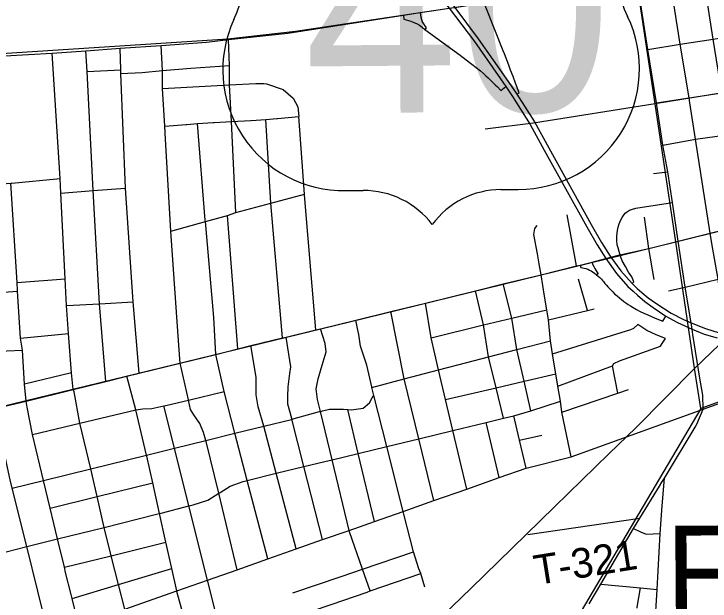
# Model space of a CAD drawing. Extents: x 114604 to 551442, y 316898 to 567001.
# Drawn here: x 189112 to 196136, y 379020 to 384943 of the extents above; entities that cross this region are included whole.
import ezdxf

# ---------------------------------------------------------------- set-up
doc = ezdxf.new("R2010")
doc.units = 0
for name, color, linetype in [('_CIVIL_CONSTRUCTION', 7, 'Continuous'), ('GE_P_Alignment_1000_Bearings', 7, 'Continuous'), ('GE_P_Alignment_1000_Cardinal_Points', 7, 'Continuous'), ('GE_P_Alignment_1000_Stations', 7, 'Continuous'), ('GE_P_Alignment_100_Cardinal_Points', 7, 'Continuous'), ('GE_P_Alignment_500_Bearings', 7, 'Continuous'), ('GE_P_Alignment_500_Cardinal_Points', 7, 'Continuous'), ('GE_P_Alignment_500_Stations', 7, 'Continuous'), ('PM_P_Crosswalk', 7, 'Continuous'), ('RD_X_RR_1', 7, 'Continuous')]:
    doc.layers.add(name, color=color, linetype=linetype)

msp = doc.modelspace()

# ---------------------------------------------------------------- linework, layer by layer
at = {"layer": '_CIVIL_CONSTRUCTION'}
for p, q in [((195595.5, 384047.1), (195925.1, 384097.7)), ((195925.1, 384097.7), (196253.8, 384147.4)), ((195660.6, 383619.4), (195595.5, 384047.1)), ((195709.9, 383351.5), (195660.6, 383619.4)), ((195756.4, 383039.5), (195709.9, 383351.5)), ((195814.7, 382651.5), (195756.4, 383039.5)), ((195884.9, 382186.6), (195814.7, 382651.5)), ((195675, 380261), (195984.7, 380773)), ((195650.1, 380220.3), (195675, 380261)), ((195426.4, 379854.5), (195625.2, 380179.7)), ((195625.2, 380179.7), (195650.1, 380220.3)), ((195363.3, 379751.9), (195426.4, 379854.5)), ((195033.9, 379188.9), (195363.3, 379751.9)), ((194916.8, 378992.5), (195033.9, 379188.9))]:
    msp.add_line(p, q, dxfattribs=at)
for points in [[(195962.4, 381707.5), (195953.8, 381761.2), (195945.8, 381825.8), (195884.9, 382186.6)], [(196067.3, 380954.6), (196064.5, 381096.7), (196032.6, 381267.8), (195962.4, 381707.5)], [(195984.7, 380773), (196002.8, 380802.8), (196067.3, 380954.6)]]:
    msp.add_lwpolyline(points, dxfattribs=at)
at = {"layer": 'GE_P_Alignment_1000_Bearings'}
for p, q in [((195580.5, 384036), (195392.5, 385288.4)), ((197578.2, 384361.5), (195580.5, 384036)), ((195789.4, 382643.8), (195580.5, 384036)), ((195789.4, 382643.8), (197558.4, 383078.4)), ((195980.4, 381370.9), (195789.4, 382643.8)), ((196041.6, 380963.5), (195980.4, 381370.9))]:
    msp.add_line(p, q, dxfattribs=at)
for points in [[(180629.5, 384002.1), (191270.2, 384690.2), (191954.5, 384767.5), (195392.5, 385288.4)], [(195580.5, 384036), (194353, 383841.5), (193865.7, 383779.9)], [(180378.1, 383822), (180652.5, 379872.3), (185830.5, 380217.5), (192483.8, 381831.8), (195789.4, 382643.8)], [(203929.1, 383849.4), (203889.4, 383842.5), (203343.8, 383747.1), (200165.3, 382456.3), (196041.6, 380963.5)], [(193435.5, 378869.9), (193724.6, 379151.4), (193997.4, 379415.8), (194279.4, 379692), (194567.9, 379971.2), (195117.6, 380508.9), (195386.9, 380768.7), (195981.6, 381368.1), (196396.9, 381765.9)], [(196041.6, 380963.5), (194033.4, 377563.3), (193868.1, 377325.2), (192058.1, 375431.3), (190340.5, 374234.8), (188290.1, 370932.4), (187383.2, 369296.1), (186211.4, 367713.7), (185191.3, 366327.4), (183802.2, 363991.4), (182496.1, 361739.6), (179755.4, 357652.8), (178697.7, 356015.2), (176027.5, 351942.2), (171808.5, 345313.1), (170010.5, 342458.8), (166009.2, 336033.6), (165560.1, 335287.7), (165457.7, 335042), (165304.5, 334515.6), (164243.2, 330883.3)]]:
    msp.add_lwpolyline(points, dxfattribs=at)
at = {"layer": 'GE_P_Alignment_1000_Cardinal_Points'}
for p, q in [((194296, 379690.6), (195426.4, 379854.5)), ((192707.6, 379121.9), (193216.4, 379297.8))]:
    msp.add_line(p, q, dxfattribs=at)
for points in [[(195363.3, 379751.9), (195435.6, 379716.6), (195489.7, 379694.5), (195633.6, 379702.5)], [(193256.4, 379159.3), (193216.4, 379297.8), (193196.4, 379346)], [(195033.9, 379188.9), (195432.5, 379152), (195603.9, 379136.1)], [(190904.9, 378491.8), (191222.7, 378600.5), (191450.2, 378678.3), (192242.1, 378961), (192313.4, 378985.6), (192675.1, 379110.7), (192707.6, 379121.9)], [(195399.1, 378949.8), (195400.7, 378959.4), (195432.5, 379152)]]:
    msp.add_lwpolyline(points, dxfattribs=at)
at = {"layer": 'GE_P_Alignment_1000_Stations'}
for p, q in [((195595.5, 384047.1), (195925.1, 384097.7)), ((195925.1, 384097.7), (196253.8, 384147.4)), ((195660.6, 383619.4), (195595.5, 384047.1)), ((195709.9, 383351.5), (195660.6, 383619.4)), ((195756.4, 383039.5), (195709.9, 383351.5)), ((195814.7, 382651.5), (195756.4, 383039.5)), ((195884.9, 382186.6), (195814.7, 382651.5)), ((195675, 380261), (195984.7, 380773)), ((195650.1, 380220.3), (195675, 380261)), ((195426.4, 379854.5), (195625.2, 380179.7)), ((195625.2, 380179.7), (195650.1, 380220.3)), ((195363.3, 379751.9), (195426.4, 379854.5)), ((195033.9, 379188.9), (195363.3, 379751.9)), ((194916.8, 378992.5), (195033.9, 379188.9))]:
    msp.add_line(p, q, dxfattribs=at)
for points in [[(189020.8, 384518.8), (189498.2, 384547.4), (189838.7, 384572.1), (190184.5, 384598.8), (190597.8, 384623.9), (191054.4, 384657.8), (191278.3, 384684.8), (191875.6, 384747.5), (193041.4, 384929.7), (193209.4, 384956), (193503.2, 385002), (193559.4, 385009.3), (193854.5, 385056.3), (194225.8, 385113.8), (194582.3, 385168.9), (194969.3, 385228.8), (195394.1, 385294.4), (195722.5, 385342.7), (196061, 385394.6), (196139.6, 385407.7)], [(195962.4, 381707.5), (195953.8, 381761.2), (195945.8, 381825.8), (195884.9, 382186.6)], [(196067.3, 380954.6), (196064.5, 381096.7), (196032.6, 381267.8), (195962.4, 381707.5)], [(195984.7, 380773), (196002.8, 380802.8), (196067.3, 380954.6)]]:
    msp.add_lwpolyline(points, dxfattribs=at)
at = {"layer": 'GE_P_Alignment_100_Cardinal_Points'}
for p, q in [((189850.7, 384361.5), (190189.4, 384378.4)), ((195566.8, 383333.3), (195709.9, 383351.5)), ((191372.5, 381563.8), (191265.8, 382910)), ((194788.6, 382401), (194693.3, 382917.1)), ((189144, 382234.2), (189629.7, 382272.1)), ((194898.7, 381951.2), (194809, 382265.6)), ((189178.4, 381671.8), (189661.5, 381718.4)), ((195203.7, 381116), (195150, 381391.5)), ((189694.4, 381322.5), (189219.5, 381207.1)), ((194009.5, 380265.7), (193876.2, 380822.7)), ((194212.9, 380641.3), (194438.5, 380692.6))]:
    msp.add_line(p, q, dxfattribs=at)
for points in [[(196528, 382337.1), (196478.8, 382649.3), (196455.3, 382783.7), (196464.6, 382810.7), (196420.2, 383077.8), (196306.8, 383722.2), (196253.8, 384147.4), (196166.9, 384689.1), (196085.5, 385207.8), (196061, 385394.6)], [(195595.5, 384047.1), (195508.2, 384584.7), (195425.8, 385104.4), (195394.1, 385294.4)], [(196239.6, 382116.5), (196235.9, 382141.4), (196217.7, 382266.3), (196155.2, 382625.3), (196137.9, 382730.2), (195989.6, 383677.9), (195933.2, 384045.1), (195925.1, 384097.7), (195834.8, 384636.3), (195754.1, 385155.2), (195722.5, 385342.7)], [(195508.2, 384584.7), (195834.8, 384636.3), (196166.9, 384689.1), (196479.7, 384738.6), (196904.7, 384805.2), (197229.1, 384855.4), (197384.9, 384878.6)], [(191352.5, 382938.6), (191306.1, 383856.9), (191287.4, 384226.4), (191286.6, 384422.4), (191278.3, 384684.8)], [(190376, 381317.9), (190315.5, 382038.5), (190237.9, 383184.4), (190191.6, 384341.5), (190189.4, 384378.4), (190184.5, 384598.8)], [(191364, 379336.4), (191178.2, 380107.8), (191052.2, 380630.6), (191049.3, 380640.5), (191025.7, 380721.4), (190987.1, 380810.3), (190926.5, 380899.7), (190893.3, 380952.4), (190873.6, 381047.7), (190872.9, 381051), (190790.2, 381418.9), (190775, 381596.8), (190695.4, 382752.4), (190641.3, 383681.1), (190633.8, 383809.3), (190611.6, 384189.1), (190610.7, 384371.1), (190597.8, 384623.9)], [(190231.2, 378936.8), (190167.7, 379187), (190094.1, 379477.5), (190021.7, 379763.2), (189950.7, 380074), (189886.6, 380354.8), (189777.5, 380814.4), (189719.3, 381130), (189709.5, 381155.1), (189694.4, 381322.5), (189661.5, 381718.4), (189643.7, 382000.9), (189629.7, 382272.1), (189585.1, 383136.1), (189577.6, 383282.2), (189498.2, 384547.4)], [(190039.7, 381236.4), (189976.5, 382019.5), (189912, 383160.3), (189850.7, 384361.5), (189838.7, 384572.1)], [(189464.6, 378670.3), (189241.5, 379569.1), (189094.7, 380160.2), (189074.1, 380243.4), (188916.2, 380962.2), (188903.5, 381154), (188880.3, 381536.3), (188819.5, 382124.2), (188768.2, 383210.6), (188749.7, 383781.6), (188718.1, 384270.1), (188707, 384499.1)], [(190191.6, 384341.5), (190405.5, 384352.5), (190610.7, 384371.1), (190895.9, 384394.8), (191286.6, 384422.4)], [(190611.6, 384189.1), (191287.4, 384226.4), (191553.3, 384241), (191634.5, 384239.6), (191661.6, 384239.1), (191827.1, 384182.1), (191927.8, 384094.1), (191976.5, 384005), (191986.8, 383906.5)], [(191506.5, 383868), (191653.4, 383876.2), (191766, 383886.4)], [(191766, 383886.4), (191771.7, 383886.9), (191986.8, 383906.5)], [(192157.6, 381757), (192043.4, 383119.4), (192042.9, 383125.2), (191986.8, 383906.5)], [(195660.6, 383619.4), (195989.6, 383677.9), (196306.8, 383722.2), (196623.4, 383766.3), (197072.9, 383829), (197376.2, 383871.3), (197531.8, 383893)], [(190633.8, 383809.3), (190850.9, 383828.1), (190856.3, 383828.6)], [(190856.3, 383828.6), (190964.9, 383837.9), (191122.1, 383846.7), (191133.6, 383847.3)], [(191673.8, 379445.2), (191466.3, 380237.2), (191341.9, 380712.4), (191232, 381132.4), (191150.7, 381508.4), (191129.8, 381878.9), (191043.4, 382848.5), (191042.4, 382861.7), (190964.9, 383837.9)], [(191133.6, 383847.3), (191306.1, 383856.9), (191501.6, 383867.8), (191506.5, 383868)], [(191822.3, 381673.8), (191703.4, 383033.4), (191653.4, 383876.2)], [(188454.9, 383185.3), (188768.2, 383210.6), (189081.8, 383235.9), (189089.4, 383236.5), (189577.6, 383282.2)], [(189736.8, 378467.4), (189710.1, 378499), (189713, 378555.2), (189738.7, 378647), (189763.8, 378712.8), (189770.7, 378760.8), (189767.4, 378774), (189698.9, 379047), (189689, 379086.4), (189633.7, 379306.9), (189620.8, 379360.4), (189551.9, 379646.4), (189477, 379957.7), (189409.6, 380237.5), (189297.9, 380701.4), (189246.4, 380976.4), (189234.6, 381037.1), (189219.5, 381207.1), (189198, 381551.6), (189178.4, 381671.8), (189149.3, 382147.7), (189149.1, 382152.2), (189144, 382234.2), (189081.8, 383235.9)], [(189585.1, 383136.1), (189912, 383160.3), (190237.9, 383184.4)], [(190695.4, 382752.4), (191043.4, 382848.5), (191265.8, 382910), (191352.5, 382938.6), (191703.4, 383033.4), (192042.9, 383125.2)], [(195814.7, 382651.5), (196137.9, 382730.2), (196464.6, 382810.7), (196767.9, 382882.3), (197139, 382975.3), (197484.6, 383057.6), (197642.4, 383096.1), (197943.9, 383168.6)], [(195571.3, 382264.6), (195516.6, 382576.9), (195473.8, 382891.2)], [(194732.9, 380476.5), (194641.9, 380926.8), (194626.9, 381036.4), (194601.2, 381188.4), (194580.1, 381313.8), (194546.8, 381511.3), (194546.2, 381515), (194525.1, 381645.3), (194504.3, 381857.2), (194489.7, 381957.8), (194467, 382094.8), (194431.6, 382310.7), (194412.6, 382422.6), (194396.2, 382524), (194357.8, 382718.1), (194366.5, 382777.3), (194390.6, 382807.9)], [(188916.2, 380962.2), (189234.6, 381037.1), (189709.5, 381155.1), (189846.3, 381189.4), (190039.7, 381236.4), (190252, 381287.5), (190376, 381317.9), (190790.2, 381418.9), (191150.7, 381508.4), (191372.5, 381563.8), (191503.4, 381596.9), (191822.3, 381673.8), (191857.8, 381681.9), (192157.6, 381757), (192205.3, 381767.7), (192561.5, 381854.5), (192913.3, 381940.4), (193264.3, 382025.4), (193769.6, 382148.8), (194049.4, 382219.4), (194431.6, 382310.7), (194788.6, 382401), (194826.8, 382409.9), (194945.5, 382439.4), (195083.5, 382474.5), (195136.1, 382487.9), (195213.5, 382507.7), (195516.6, 382576.9), (195814.7, 382651.5)], [(195717.6, 382149), (195884.9, 382186.6), (196217.7, 382266.3), (196370.2, 382301.3), (196528, 382337.1), (196834.7, 382420.1)], [(194326.7, 380940.2), (194258.6, 381238.2), (194185.7, 381557.7), (194134.4, 381874.5), (194049.4, 382219.4)], [(188170.2, 382077.8), (188517.8, 382102.6), (188819.5, 382124.2), (189149.3, 382147.7)], [(194052.4, 380863.7), (193976.8, 381172), (193900.4, 381484), (193850.1, 381806.5), (193769.6, 382148.8)], [(189643.7, 382000.9), (189976.5, 382019.5), (190315.5, 382038.5)], [(193681.1, 380150.3), (193540.5, 380741.2), (193466.6, 381052.1), (193397, 381352.3), (193322.3, 381674.8), (193264.3, 382025.4)], [(193349.2, 380033.7), (193197.3, 380657.9), (193050.6, 381260.7), (192913.3, 381940.4)], [(193322.3, 381674.8), (193850.1, 381806.5), (194134.4, 381874.5), (194489.7, 381957.8)], [(194504.3, 381857.2), (194898.7, 381951.2), (194967.1, 381968.2)], [(193196.4, 379346), (193142.8, 379515.1), (193045.8, 379897.3), (193038.9, 379924.7), (192872.9, 380579.1), (192744.3, 381093.4), (192724, 381174.4), (192722.2, 381181.6), (192671.8, 381399.1), (192608.9, 381592.8), (192592.9, 381708.9), (192578.6, 381767.8), (192561.5, 381854.5)], [(194546.2, 381515), (195335.7, 381759.1), (195366.8, 381773.8), (195408.7, 381808.9)], [(195685.9, 381670.2), (195592.4, 381706.4), (195498.6, 381748.9), (195408.7, 381808.9)], [(192707.6, 379121.9), (192630.6, 379341.5), (192498.6, 379718.2), (192493.3, 379733.1), (192321.7, 380445.3), (192204, 380933.6), (192174.5, 381052.6), (192160.3, 381161.2), (192180.1, 381263.2), (192220.6, 381398.9), (192261, 381534.6), (192252.4, 381619), (192205.3, 381767.7)], [(192226.7, 379639.4), (192038.3, 380376.4), (191916.3, 380853.6), (191914.5, 380860.5), (191876.9, 381007.6), (191876.2, 381081.9), (191879.9, 381182.1), (191896.2, 381314.2), (191905.4, 381382.3), (191896.5, 381446.6), (191885.5, 381509), (191857.8, 381681.9)], [(192724, 381174.4), (193050.6, 381260.7), (193397, 381352.3), (193683, 381427.9), (193900.4, 381484), (194185.7, 381557.7), (194525.1, 381645.3)], [(194601.2, 381188.4), (195150, 381391.5), (195166.5, 381416.7), (195221.6, 381443.9), (195634.5, 381592.8), (195652.8, 381618), (195685.9, 381670.2)], [(191958.1, 379545.1), (191758.9, 380308.4), (191634.7, 380784.3), (191577.6, 380978.7), (191557.6, 381099.4), (191554.6, 381274), (191529.4, 381440.9), (191503.4, 381596.9)], [(188209.4, 381474.8), (188554.7, 381504.9), (188880.3, 381536.3), (189198, 381551.6)], [(196067.3, 380954.6), (196412.7, 381079.2), (196846.6, 381245.5), (196994.9, 381298.1), (197209.1, 381374.1), (197295, 381404.5), (197348.5, 381423.5)], [(190898.2, 378550.7), (190865, 378717.8), (190756.1, 379117.2), (190754.7, 379122.4), (190704.6, 379347.4), (190645.3, 379613.8), (190581.1, 379902.4), (190512.3, 380211.8), (190452, 380482.5), (190449.6, 380493.1), (190343.1, 380947.7), (190252, 381287.5)], [(193466.6, 381052.1), (193976.8, 381172), (194258.6, 381238.2), (194580.1, 381313.8)], [(194641.9, 380926.8), (195203.7, 381116), (195313.9, 381153.2)], [(189094.7, 380160.2), (189409.6, 380237.5), (189886.6, 380354.8), (190449.6, 380493.1), (190732.3, 380562.5), (191049.3, 380640.5), (191341.9, 380712.4), (191634.7, 380784.3), (191912.3, 380852.5), (191916.3, 380853.6), (192196.5, 380931.9), (192204, 380933.6), (192226.7, 380938.6), (192297.1, 380954.2), (192437.6, 380955.8), (192480, 380952.9), (192517.7, 380950.4), (192634.2, 380964.4), (192699.4, 381019.5), (192726.3, 381069.2), (192744.3, 381093.4)], [(189297.9, 380701.4), (189777.5, 380814.4), (190343.1, 380947.7), (190414.1, 380958.7), (190504.4, 380961.1), (190625.6, 380989.2), (190657.4, 380996.6), (190873.6, 381047.7), (191232, 381132.4)], [(188924.6, 379490.3), (189241.5, 379569.1), (189551.9, 379646.4), (190021.7, 379763.2), (190550.7, 379894.8), (190581.1, 379902.4), (190596.6, 379906.2), (190878, 379979.7), (190920.9, 379990.9), (191068.1, 380036.5), (191178.2, 380107.8), (191191.8, 380116.6), (191295.1, 380179), (191424.3, 380227), (191466.3, 380237.2), (191758.9, 380308.4), (192038.3, 380376.4), (192248, 380427.4), (192321.7, 380445.3), (192585.7, 380509.4), (192872.9, 380579.1), (193197.3, 380657.9), (193540.5, 380741.2), (193876.2, 380822.7), (194052.4, 380863.7), (194154.9, 380888.5), (194326.7, 380940.2), (194626.9, 381036.4)], [(191222.7, 378600.5), (191065, 379231.4), (190878, 379979.7), (190732.3, 380562.5), (190625.6, 380989.2)], [(190754.7, 379122.4), (191065, 379231.4), (191364, 379336.4), (191673.8, 379445.2), (191958.1, 379545.1), (192226.7, 379639.4), (192493.3, 379733.1), (192749.3, 379823), (193038.9, 379924.7), (193349.2, 380033.7), (193681.1, 380150.3), (194009.5, 380265.7), (194278.9, 380360.3), (194732.9, 380476.5), (196067.3, 380954.6)], [(192749.3, 379823), (192585.7, 380509.4), (192480, 380952.9)], [(194278.9, 380360.3), (194212.9, 380641.3), (194154.9, 380888.5)], [(189477, 379957.7), (189950.7, 380074), (190512.3, 380211.8)], [(189620.8, 379360.4), (190094.1, 379477.5), (190645.3, 379613.8)], [(191926.4, 379102.8), (192413, 379267.7), (192630.6, 379341.5), (193142.8, 379515.1)], [(189698.9, 379047), (190167.7, 379187), (190704.6, 379347.4)], [(185409.7, 378881.1), (185731.1, 378839.2), (185741.4, 378837.8), (186033.6, 378798.8), (186319.5, 378760.6), (186330, 378758.3), (186675.7, 378685.2), (187054.4, 378602.2), (187424.5, 378526.3), (187803.7, 378445.8), (187812.7, 378443.7), (188179.5, 378361.3), (188527.8, 378283.1), (188628.3, 378266.7), (188658.4, 378263.2), (188688.3, 378271.7), (189464.6, 378670.3), (189767.4, 378774), (189899.9, 378819.3), (190231.2, 378936.8), (190754.7, 379122.4)]]:
    msp.add_lwpolyline(points, dxfattribs=at)
at = {"layer": 'GE_P_Alignment_500_Bearings'}
msp.add_line((195654.3, 379981.7), (195675, 380261), dxfattribs=at)
msp.add_lwpolyline([(195375.2, 374985.3), (195396.6, 375314), (195418.9, 375689.3), (195435.9, 376124.6), (195457.9, 376552.6), (195479.9, 376980.3), (195497.5, 377323.3), (195514.3, 377650.3), (195523.2, 377822.6), (195543.3, 378150.2), (195580.4, 378752.4), (195603.9, 379136.1), (195633.6, 379702.5), (195654.3, 379981.7)], dxfattribs=at)
at = {"layer": 'GE_P_Alignment_500_Cardinal_Points'}
for p, q in [((193258.9, 384786.7), (193614, 384525.9)), ((192460.2, 383160.1), (192634.2, 383161.4)), ((194026.5, 383171.4), (194200.5, 383172.7))]:
    msp.add_line(p, q, dxfattribs=at)
for points in [[(194060.7, 384539.2), (194048.2, 384570.1), (193871.9, 385011.4), (193854.5, 385056.3)], [(193209.4, 384956), (193216.6, 384908.8), (193222.9, 384885.3), (193232.2, 384861.7), (193243.1, 384841.3), (193253.6, 384825.4), (193271.5, 384803.9), (193258.9, 384786.7)], [(193041.4, 384929.7), (193047.6, 384888.7), (193117.5, 384868.8), (193147.4, 384857.5), (193173.3, 384845.3), (193203.2, 384828.2), (193229.5, 384810), (193258.9, 384786.7)], [(193614, 384525.9), (193631.8, 384512.9), (193733.1, 384436.9), (193819.4, 384369.8), (193849.9, 384341.5), (193873.2, 384319.7), (193895.5, 384298.4), (193921.6, 384273.3), (193946.7, 384248.8), (193968.6, 384227.1), (193989.6, 384206), (194024, 384171.1), (194076.8, 384211.6)], [(194185.9, 384133), (194210.8, 384146.8), (194174.3, 384243.3), (194148.4, 384310.6), (194124, 384376.7), (194106.4, 384426), (194060.7, 384539.2)], [(195349.4, 382222.4), (195366.7, 382241), (195346.9, 382290.1), (195314, 382336.6), (195281.1, 382393.8), (195250.3, 382453.3), (195235.9, 382489), (195228.3, 382511.1), (195224.4, 382523.4), (195218.1, 382545.3), (195208.1, 382584.3), (195200.3, 382614.6), (195194.5, 382653.7), (195195.2, 382697.8), (195199.3, 382735.6), (195203.2, 382759.2), (195210.3, 382792), (195220, 382826.4), (195231.2, 382858.6), (195249.3, 382889.5), (195268.6, 382917.9), (195280.4, 382932.1), (195293, 382942.7), (195302, 382949.6), (195322.5, 382962.8), (195353.9, 382974.9), (195388.6, 382984.9), (195756.4, 383039.5)], [(194826.8, 382409.9), (194830.8, 382384.2), (194865.2, 382378.1), (194881.4, 382374), (194902, 382367.1), (194920.9, 382358.9), (194935.5, 382351.3), (194950.7, 382342), (194965.7, 382331.1), (194989.7, 382311.3)], [(194945.5, 382439.4), (194949.6, 382418.8), (194961.6, 382395.7), (194973.9, 382373.2), (194983.3, 382357.1), (194993.1, 382340.8), (195005.4, 382321.3), (194989.7, 382311.3)], [(194989.7, 382311.3), (195024.3, 382283.9), (195041.5, 382266.5), (195052.1, 382254.3), (195059.5, 382244.9), (195075.8, 382224.4), (195090.5, 382206.8), (195104.5, 382190.8), (195121.4, 382172.1), (195137.2, 382155.5), (195153.7, 382138.9), (195173.2, 382120.2), (195198.1, 382097.6), (195220.9, 382078.1), (195241.9, 382061.1), (195262.1, 382045.6), (195266.9, 382042.1)], [(195266.9, 382042.1), (195286.1, 382028.1), (195308.9, 382012.4), (195332.8, 381996.8), (195360.3, 381980.1), (195393.8, 381961), (195429.9, 381942.3), (195467, 381924.9), (195509.2, 381907.1), (195581.7, 381873.6), (195660.2, 381841.9), (195690, 381895.2)]]:
    msp.add_lwpolyline(points, dxfattribs=at)
for centre, radius, start, end in [((196400.3, 385448.4), 1218.2, 145.41233, 205.86613), ((190227.8, 385403.9), 1218.2, 334.96035, 35.41416), ((192437.8, 384378.1), 1218.2, 155.24514, 271.05149), ((194205.3, 384390.9), 1218.2, 269.77499, 25.58134), ((192640.5, 382291.2), 870.2, 37.28314, 90.41324), ((194032.7, 382301.3), 870.2, 90.41324, 143.54334)]:
    msp.add_arc(centre, radius, start, end, dxfattribs=at)
at = {"layer": 'GE_P_Alignment_500_Stations'}
for points in [[(193301, 385249), (193356.8, 385181.2), (193503.2, 385002), (193759.4, 384665.7), (194076.8, 384211.6), (194141.5, 384108.4), (194319.7, 383828.6), (194463.6, 383567.3), (194891.7, 382794.9), (194995.8, 382612.2), (195083.5, 382474.5), (195191.1, 382325.9), (195307.4, 382194.7), (195359.2, 382146.5), (195403.9, 382105.1), (195478, 382043.1), (195561.9, 381979.8), (195690, 381895.2), (195809, 381828.7), (195953.8, 381761.2), (196076.6, 381713.8), (196206.2, 381674.5)], [(193342.5, 385272.6), (193395, 385208.8), (193559.4, 385009.3), (193797.6, 384693.3), (194099.7, 384261.2), (194185.9, 384133), (194364.2, 383853.3), (194508.1, 383591.9), (194936.1, 382819.5), (195040.3, 382636.8), (195128, 382499.1), (195136.1, 382487.9), (195235.5, 382350.5), (195349.4, 382222.4), (195401.2, 382174.2), (195446, 382132.8), (195511.6, 382078.1), (195598.5, 382019.8), (195743.7, 381923.6), (195867, 381860.6), (195945.8, 381825.8), (196088.7, 381770.8), (196226.6, 381726.6)]]:
    msp.add_lwpolyline(points, dxfattribs=at)

# ---------------------------------------------------------------- texts
at = {"layer": 'GE_P_Alignment_500_Cardinal_Points'}
msp.add_text('40', height=2088.4, rotation=0.41324, dxfattribs=at).set_placement((192043.2, 383940.3))
at = {"layer": 'GE_P_Alignment_500_Stations'}
msp.add_text('FRANKLIN', height=900.05, rotation=0.41329, dxfattribs=at).set_placement((195692.5, 378878.3))
at = {"layer": 'PM_P_Crosswalk'}
msp.add_text('T-321', height=300.02, rotation=9.13762, dxfattribs=at).set_placement((194384.2, 379180.3))
at = {"layer": 'RD_X_RR_1'}
msp.add_text('40', height=1, rotation=0.41324, dxfattribs=at).set_placement((193112, 384769.7))

doc.saveas('drawing.dxf')
